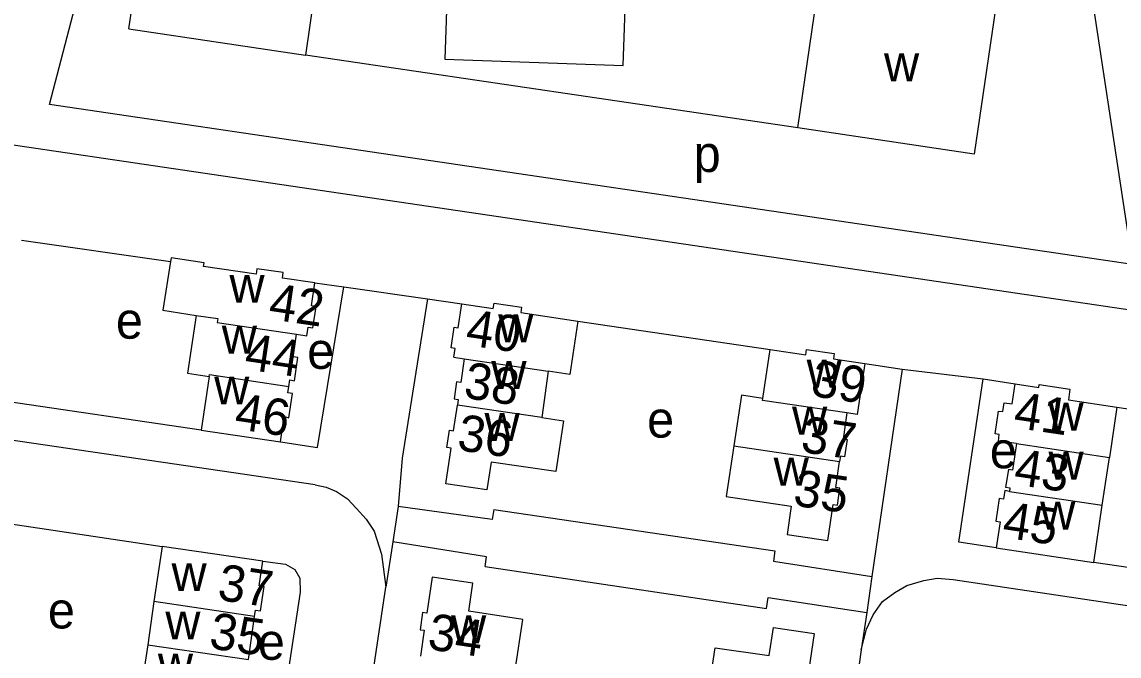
# Model space of a CAD drawing. Extents: x 163012 to 165277, y 382513 to 383987.
# Drawn here: x 164248.2 to 164368.9, y 383009.8 to 383079.5 of the extents above; entities that cross this region are included whole.
import ezdxf

# ---------------------------------------------------------------- set-up
doc = ezdxf.new("R2010")
doc.units = 0
for name, color, linetype in [('BLT_Basislijn', 7, 'Continuous'), ('BLT_Bebouwing', 7, 'Continuous'), ('BLT_Centroide', 7, 'Continuous'), ('BLT_Huisnummer', 7, 'Continuous'), ('BLT_Huisnummer_ tussenligend', 7, 'Continuous'), ('BLT_Onderverdeling_panden', 7, 'Continuous')]:
    doc.layers.add(name, color=color, linetype=linetype)

msp = doc.modelspace()

# ---------------------------------------------------------------- linework, layer by layer
at = {"layer": 'BLT_Basislijn'}
for p, q in [((164333.52, 383067.87), (164279.36, 383075.89)), ((164603.19, 383013.36), (164235.92, 383067.64)), ((164248.15, 383055.53), (164264.52, 383053.16)), ((164280.39, 383050.84), (164283.58, 383050.38)), ((164283.58, 383050.38), (164292.78, 383049.05)), ((164292.78, 383049.05), (164296.56, 383048.51)), ((164309.34, 383046.61), (164330.49, 383043.49)), ((164340.89, 383041.94), (164345.01, 383041.32)), ((164345.01, 383041.32), (164341.68, 383018.51)), ((164345.01, 383041.32), (164353.92, 383040.25)), ((164353.92, 383040.25), (164357.44, 383039.72)), ((164267.89, 383034.63), (164243.25, 383038.25)), ((164368.63, 383037.16), (164389.96, 383033.96)), ((164280.44, 383028.59), (164229.48, 383036.11)), ((164289.56, 383026.21), (164288.99, 383022.33)), ((164300.1, 383025.87), (164331.01, 383021.32)), ((164241.28, 383025.17), (164263.6, 383021.82)), ((164288.99, 383022.33), (164288.2, 383017.35)), ((164299.13, 383019.61), (164330.1, 383014.99)), ((164386.22, 383017.06), (164366.08, 383020.07)), ((164341.68, 383018.51), (164341.11, 383014.55)), ((164275.97, 382934.52), (164288.2, 383017.35)), ((164341.11, 383014.55), (164340.51, 383010.46)), ((164340.51, 383010.46), (164328.28, 382926.74))]:
    msp.add_line(p, q, dxfattribs=at)
for points in [[(164359.03, 383106.48), (164362.13, 383106.93), (164370.33, 383052.83)], [(164370.33, 383052.83), (164251.23, 383070.43), (164259.63, 383102.63), (164263.34, 383101.65)], [(164276.63, 383033.33), (164280.7, 383032.72), (164283.58, 383050.38)], [(164292.78, 383049.05), (164290.01, 383031.53), (164289.56, 383026.21)], [(164355.35, 383021.67), (164351.24, 383022.28), (164353.92, 383040.25)], [(164280.44, 383028.59), (164281.63, 383028.36), (164282.79, 383027.88), (164284, 383027.07), (164285, 383026.01), (164286.05, 383024.83), (164286.91, 383023.5), (164287.72, 383020.96), (164288.2, 383017.35)], [(164300.1, 383025.87), (164299.9, 383024.78), (164289.56, 383026.21)], [(164299.13, 383019.61), (164299.3, 383020.69), (164288.99, 383022.33)], [(164331.01, 383021.32), (164330.86, 383020.19), (164341.68, 383018.51)], [(164274.68, 383020.19), (164277.19, 383019.87), (164278.19, 383019.29), (164278.74, 383018.33), (164278.78, 383016.8), (164275.54, 382995.25)], [(164340.51, 383010.46), (164341.09, 383012.72), (164341.82, 383014.3), (164342.85, 383015.75), (164344.2, 383016.75), (164345.53, 383017.52), (164347.39, 383018.09), (164348.84, 383018.34), (164350.62, 383018.17), (164401.43, 383010.61), (164402.91, 383010.27), (164404.33, 383009.72), (164405.54, 383009.03), (164406.65, 383008.08), (164407.71, 383006.32), (164408.24, 383004.59), (164408.61, 383002.5), (164408.7, 383000.32)], [(164330.1, 383014.99), (164330.26, 383016.2), (164341.11, 383014.55)]]:
    msp.add_lwpolyline(points, dxfattribs=at)
at = {"layer": 'BLT_Bebouwing'}
for p, q in [((164285.13, 383115.03), (164279.36, 383075.89)), ((164333.52, 383067.87), (164339.9, 383111.29)), ((164259.94, 383078.76), (164279.36, 383075.89)), ((164352.92, 383064.99), (164333.52, 383067.87)), ((164295.7, 383042.66), (164296.84, 383042.48)), ((164334.5, 383043.49), (164337.52, 383043.06)), ((164306.07, 383041.11), (164305.38, 383036.01)), ((164308.46, 383040.75), (164306.07, 383041.11)), ((164360.08, 383039.65), (164363.46, 383039.14)), ((164367.02, 383026.37), (164367.8, 383031.61))]:
    msp.add_line(p, q, dxfattribs=at)
msp.add_lwpolyline([(164295.86, 383109.65), (164294.7, 383075.42), (164314.31, 383074.74), (164315.51, 383108.98)], close=True, dxfattribs=at)
for points in [[(164359.03, 383106.48), (164352.92, 383064.99)], [(164259.94, 383078.76), (164263.34, 383101.65)], [(164280.39, 383050.84), (164276.84, 383051.33), (164276.92, 383051.95), (164274.02, 383052.37), (164273.94, 383051.79), (164268.17, 383052.62), (164268.23, 383053.01), (164264.59, 383053.59), (164264.52, 383053.16)], [(164264.52, 383053.16), (164263.67, 383047.83), (164267.35, 383047.24)], [(164278.39, 383045.17), (164279.52, 383045.01), (164279.67, 383045.94), (164280.19, 383045.88), (164280.54, 383048.2), (164280.03, 383048.28), (164280.39, 383050.84)], [(164296.56, 383048.51), (164300.03, 383047.99), (164300.12, 383048.59), (164303.12, 383048.14)], [(164295.7, 383042.66), (164295.84, 383043.6), (164295.39, 383043.67), (164295.73, 383045.95), (164296.18, 383045.88), (164296.56, 383048.51)], [(164303.12, 383048.14), (164303.05, 383047.57), (164309.34, 383046.61)], [(164267.35, 383047.24), (164266.4, 383040.87), (164268.78, 383040.52)], [(164309.34, 383046.61), (164308.46, 383040.75)], [(164277.53, 383039.43), (164277.64, 383040.14), (164278.17, 383040.06), (164278.55, 383042.61), (164278.01, 383042.69), (164278.39, 383045.17)], [(164296.84, 383042.48), (164296.45, 383039.87), (164296, 383039.93), (164295.73, 383038.06), (164296.17, 383037.99), (164296.08, 383037.37)], [(164329.68, 383038.11), (164330.49, 383043.49)], [(164330.49, 383043.49), (164334.4, 383042.91), (164334.5, 383043.49)], [(164337.52, 383043.06), (164337.45, 383042.46), (164340.89, 383041.94)], [(164340.89, 383041.94), (164340.06, 383036.33), (164338.91, 383036.51)], [(164268.78, 383040.52), (164267.89, 383034.63)], [(164276.63, 383033.33), (164277.04, 383036.1), (164277.56, 383035.98), (164277.96, 383038.64), (164277.42, 383038.72), (164277.53, 383039.43)], [(164357.57, 383033.15), (164355.59, 383033.42), (164355.69, 383034.13), (164355.23, 383034.2), (164355.61, 383036.72), (164356.07, 383036.65), (164356.22, 383037.63), (164357.11, 383037.51), (164357.44, 383039.72)], [(164357.44, 383039.72), (164360.04, 383039.32), (164360.08, 383039.65)], [(164363.46, 383039.14), (164363.29, 383037.95), (164368.63, 383037.16)], [(164329.68, 383038.11), (164327.32, 383038.47), (164326.49, 383032.88)], [(164305.38, 383036.01), (164307.74, 383035.65), (164306.92, 383030.07), (164299.79, 383031.1), (164299.32, 383028.04), (164294.81, 383028.7), (164295.38, 383032.65), (164294.93, 383032.71), (164295.21, 383034.6), (164295.66, 383034.54), (164296.08, 383037.37)], [(164338.91, 383036.51), (164338.5, 383033.64), (164338.94, 383033.57), (164338.66, 383031.69), (164338.22, 383031.76), (164338.13, 383031.16)], [(164368.63, 383037.16), (164367.8, 383031.61)], [(164267.89, 383034.63), (164276.63, 383033.33)], [(164326.49, 383032.88), (164325.66, 383027.31), (164332.78, 383026.26), (164332.35, 383023.14), (164336.84, 383022.47), (164337.43, 383026.43), (164337.88, 383026.37), (164338.15, 383028.25), (164337.71, 383028.32), (164338.13, 383031.16)], [(164357.57, 383033.15), (164357.13, 383030.23), (164356.69, 383030.3), (164356.39, 383028.36), (164356.85, 383028.28), (164356.8, 383027.88)], [(164356.8, 383027.88), (164356.3, 383027.96), (164356.15, 383027.03), (164355.68, 383027.11), (164355.3, 383024.59), (164355.77, 383024.52), (164355.35, 383021.67)], [(164366.08, 383020.07), (164367.02, 383026.37)], [(164263.6, 383021.82), (164262.71, 383015.77)], [(164274.68, 383020.19), (164263.6, 383021.82)], [(164355.35, 383021.67), (164366.08, 383020.07)], [(164274.42, 383014.73), (164274.82, 383017.4), (164274.28, 383017.48), (164274.68, 383020.19)], [(164301.26, 383008.42), (164302.45, 383008.21), (164303.28, 383013.79), (164297.33, 383014.69), (164297.79, 383017.77), (164293.3, 383018.43), (164292.71, 383014.48), (164292.26, 383014.54), (164291.98, 383012.66), (164292.43, 383012.6), (164292.01, 383009.76)], [(164262.71, 383015.77), (164262.02, 383011.01)], [(164273.78, 383014.13), (164273.89, 383014.81)], [(164273.89, 383014.81), (164274.42, 383014.73)], [(164273.09, 383009.38), (164273.78, 383014.13)], [(164323.63, 383005.34), (164324.42, 383010.66), (164330.37, 383009.81), (164330.84, 383012.89), (164335.31, 383012.23), (164334.73, 383008.28), (164335.18, 383008.22), (164334.9, 383006.36), (164334.47, 383006.42), (164334.04, 383003.53)], [(164262.02, 383011.01), (164261.28, 383006), (164263.65, 383005.65)]]:
    msp.add_lwpolyline(points, dxfattribs=at)
at = {"layer": 'BLT_Onderverdeling_panden'}
for p, q in [((164296.84, 383042.48), (164306.07, 383041.11)), ((164305.38, 383036.01), (164296.08, 383037.37)), ((164326.49, 383032.88), (164338.13, 383031.16)), ((164357.57, 383033.15), (164367.8, 383031.61)), ((164356.8, 383027.88), (164367.02, 383026.37))]:
    msp.add_line(p, q, dxfattribs=at)
for points in [[(164267.35, 383047.24), (164269.72, 383046.89), (164269.66, 383046.46), (164278.39, 383045.17)], [(164268.78, 383040.52), (164268.81, 383040.73), (164277.53, 383039.43)], [(164338.91, 383036.51), (164329.64, 383037.87), (164329.68, 383038.11)], [(164273.78, 383014.13), (164262.71, 383015.77)], [(164262.02, 383011.01), (164273.09, 383009.38)]]:
    msp.add_lwpolyline(points, dxfattribs=at)

# ---------------------------------------------------------------- texts
at = {"layer": 'BLT_Centroide'}
for s, p in [('w', (164343.01, 383073)), ('p', (164322.07, 383063.02)), ('w', (164271.01, 383048.63)), ('e', (164258.52, 383044.68)), ('w', (164300.57, 383044.28)), ('w', (164270.17, 383043.03)), ('e', (164279.56, 383041.36)), ('w', (164299.82, 383039.14)), ('w', (164334.5, 383039.3)), ('w', (164269.33, 383037.44)), ('w', (164299.07, 383033.42)), ('e', (164316.95, 383033.8)), ('w', (164332.9, 383034.12)), ('w', (164361.1, 383034.57)), ('e', (164354.65, 383030.42)), ('w', (164361.1, 383029.17)), ('w', (164330.87, 383028.5)), ('w', (164360.19, 383023.66)), ('w', (164264.64, 383016.9)), ('e', (164251.04, 383012.8)), ('w', (164263.96, 383011.59)), ('w', (164295.39, 383011.17)), ('e', (164274.13, 383009.35)), ('w', (164263.14, 383006.95))]:
    msp.add_text(s, height=4, dxfattribs=at).set_placement(p)
at = {"layer": 'BLT_Huisnummer'}
for s, rotation, p in [('42', 351.583, (164275.2, 383046.86)), ('40', 351.581, (164296.87, 383044)), ('39', 351.583, (164334.85, 383038.4)), ('46', 351.583, (164271.45, 383034.78)), ('41', 351.581, (164357.15, 383034.91)), ('36', 351.583, (164295.94, 383032.45)), ('35', 351.583, (164332.9, 383026.35)), ('45', 351.583, (164355.92, 383022.84)), ('37', 351.581, (164269.58, 383015.97)), ('34', 351.583, (164292.69, 383010.54))]:
    msp.add_text(s, height=4, rotation=rotation, dxfattribs=at).set_placement(p)
at = {"layer": 'BLT_Huisnummer_ tussenligend'}
for s, rotation, p in [('44', 351.583, (164272.55, 383041.34)), ('38', 351.581, (164296.66, 383038.19)), ('37', 351.583, (164333.73, 383032.24)), ('43', 351.581, (164357.18, 383028.66)), ('35', 351.581, (164268.66, 383010.64))]:
    msp.add_text(s, height=4, rotation=rotation, dxfattribs=at).set_placement(p)

doc.saveas('drawing.dxf')
